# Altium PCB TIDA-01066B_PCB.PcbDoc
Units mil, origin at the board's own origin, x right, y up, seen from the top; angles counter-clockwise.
Board outline 2100 x 1400 mil, 2 copper layers (Top Layer, Bottom Layer), stack 62 mil thick; 43 components, 17 nets, 105 pads, 10 vias.
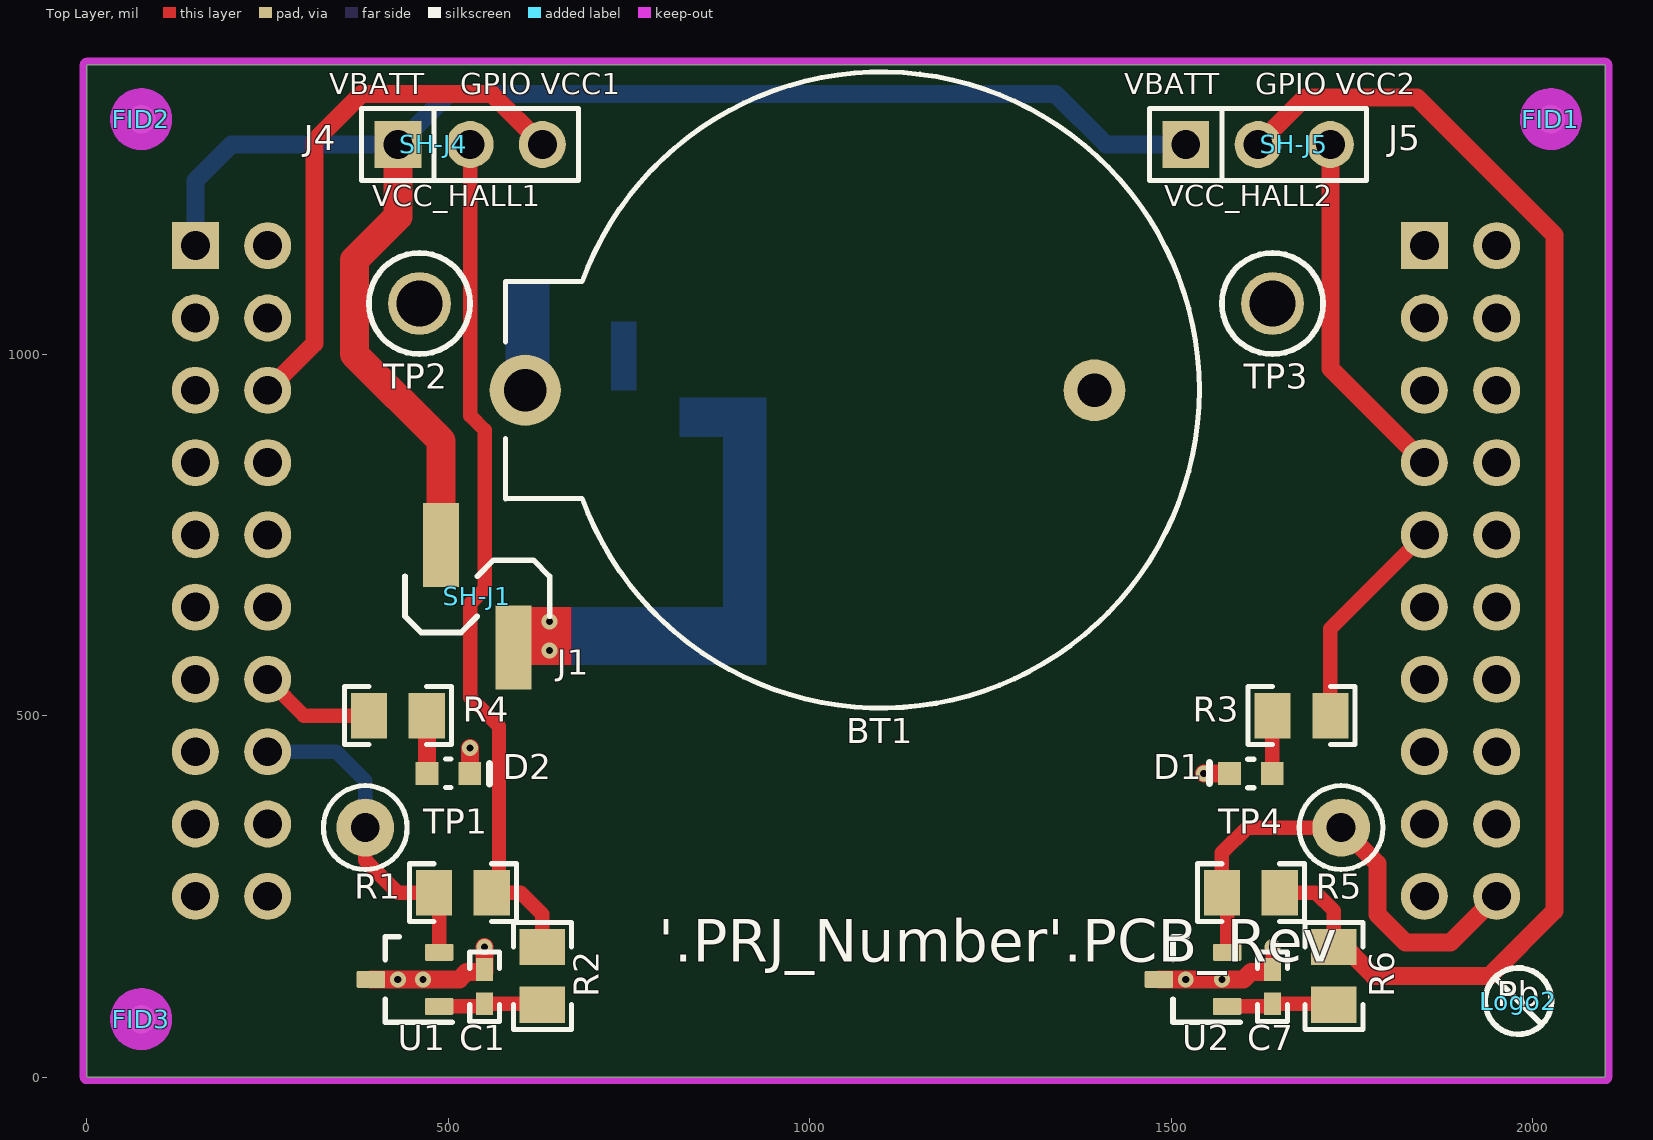
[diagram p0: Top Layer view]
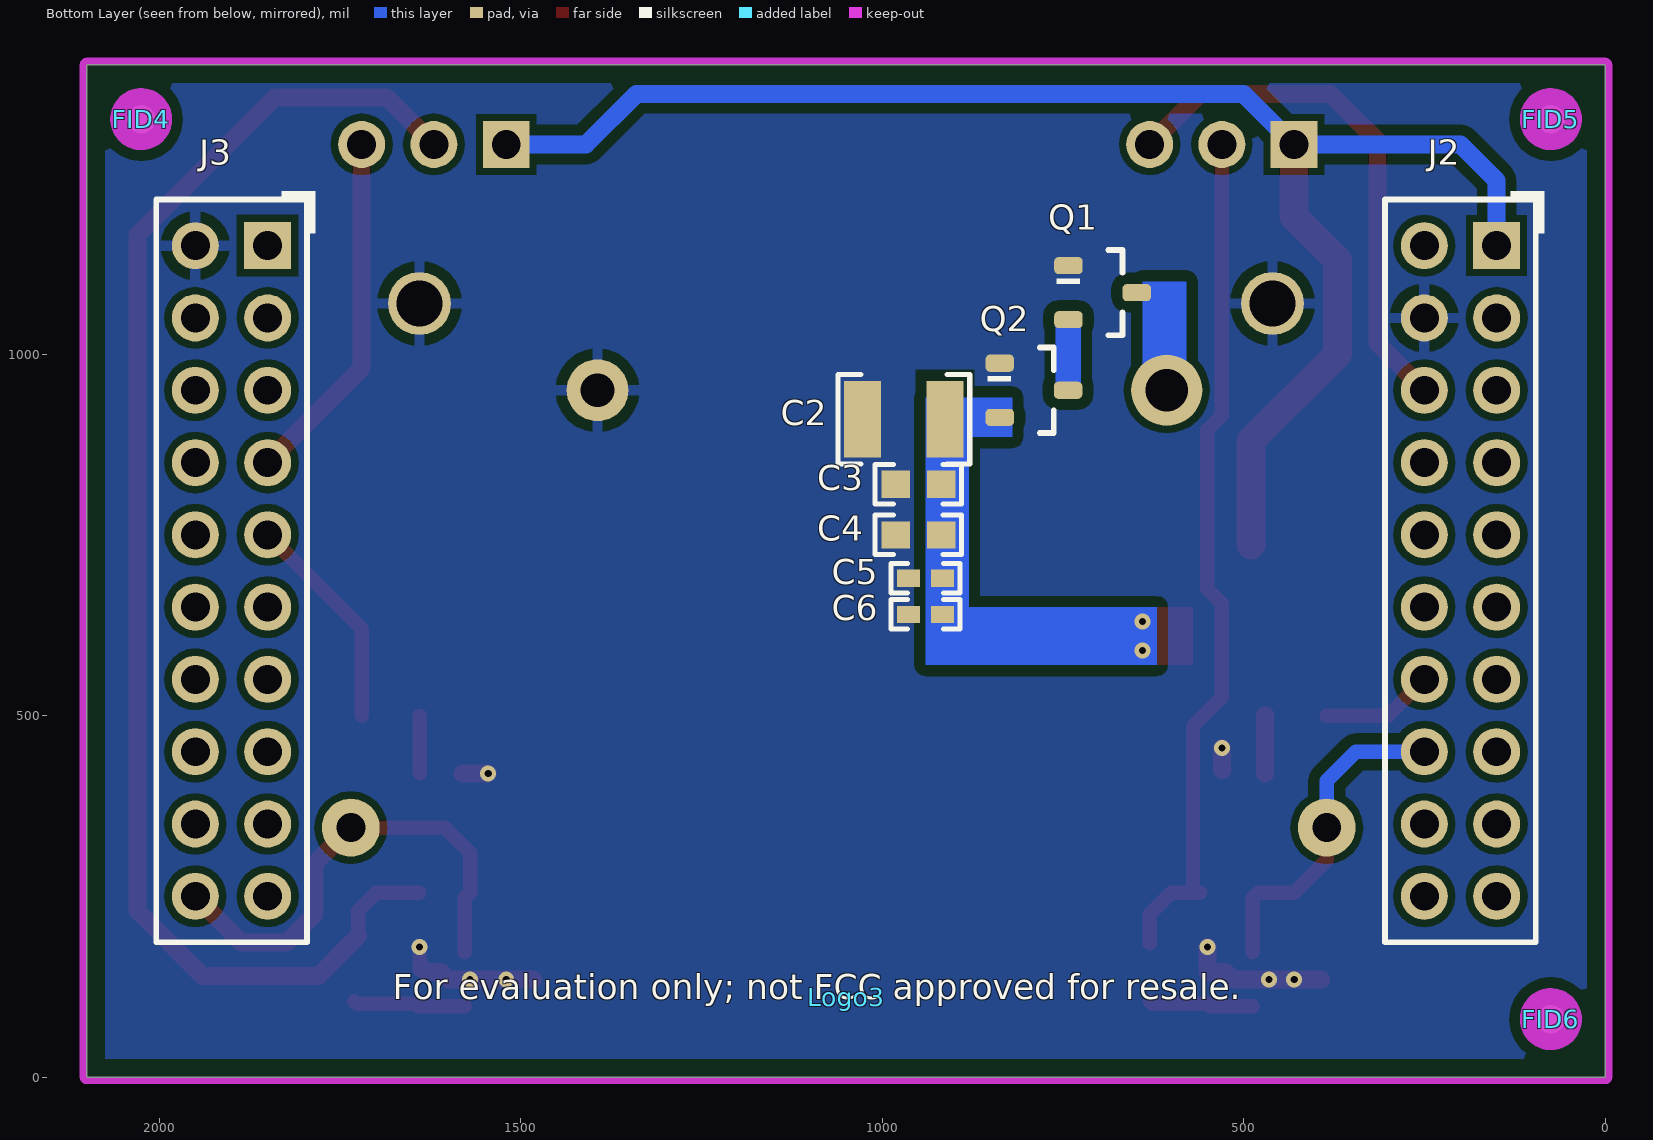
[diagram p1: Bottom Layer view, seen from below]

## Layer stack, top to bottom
Top Solder: solder mask 0.4, Solder Resist, Dk 3.5
Top Layer: signal copper 1.4
Dielectric1: core 59.2, FR-4, Dk 4.8
Bottom Layer: signal copper 1.4
Bottom Solder: solder mask 0.4, Solder Resist, Dk 3.5

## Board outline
0,0 0,1400 2100,1400 2100,0

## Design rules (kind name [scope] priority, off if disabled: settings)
AcuteAngle [All] p1: minimum=4.50000000000000E+0001 checktracksonly=FALSE
AssemblyTestPointUsage [All] p1: valid=2
BoardOutlineClearance BoardOutlineClearance_MountingHoles [OnCopper and InComponentClass('Mounting Holes')] p1: gap=40
BoardOutlineClearance BoardOutlineClearance_Poly [OnCopper and InPoly] p2: gap=25
BoardOutlineClearance [OnCopper and Not InComponentClass('Logo') and not InComponentClass('FiducialMark') and not InRegion(1000,500,4000,800)] p3: gap=25
Clearance Clearance_Keepouts [((IsTrack Or IsArc) And Not InPoly) And IsFree and IsKeepOut vs ((IsTrack Or IsArc) And Not InPoly) And IsFree and IsKeepOut] p1: gap=0
Clearance Clearance_Poly [InPolygon] p2: gap=15 except(10: THPad-Poly)
Clearance [All] p3: gap=7.87
ComponentClearance ComponentClearance_MountingHoles_FiducialMarks [InComponentClass('Mounting Holes') vs InComponentClass('FiducialMark')] p1: gap=50 collisioncheckmode=3 verticalgap=10 showdistances=FALSE
ComponentClearance ComponentClearance_Shunt [InComponentClass('Header') vs InComponentClass('Shunt')] p2: gap=0 collisioncheckmode=3 verticalgap=0 showdistances=FALSE
ComponentClearance ComponentClearance_Logo [InComponentClass('Logo')] p3: gap=0 collisioncheckmode=3 verticalgap=0 showdistances=FALSE
ComponentClearance ComponentClearance_ScrewToNut [(HasFootprint('NY PMS 440 0025 PH')) vs (HasFootprint('Keystone_1902C'))] p4: gap=5 collisioncheckmode=3 verticalgap=10 showdistances=FALSE
ComponentClearance ComponentClearance_MountingHoles [InComponentClass('Mounting Holes')] p5: gap=250 collisioncheckmode=3 verticalgap=100000 showdistances=FALSE
ComponentClearance ComponentClearance_SmallPassives [HasFootprint('0201*') or HasFootprint('0402*') or HasFootprint('0508') or HasFootprint('0603*') or HasFootprint('0612') or HasFootprint('0805*') or HasFootprint('0815*') or HasFootprint('0830*') or HasFootprint('1206*') or HasFootprint('1210*') or HasFootprint('1808*') or HasFootprint('1812*') or HasFootprint('1825*') or HasFootprint('2010*') or HasFootprint('2220*') or HasFootprint('2225*') or HasFootprint('2512*') or HasFootprint('2728*') or HasFootprint('3518*') vs HasFootprint('0201*') or HasFootprint('0402*') or HasFootprint('0508') or HasFootprint('0603*') or HasFootprint('0612') or HasFootprint('0805*') or HasFootprint('0815*') or HasFootprint('0830*') or HasFootprint('1206*') or HasFootprint('1210*') or HasFootprint('1808*') or HasFootprint('1812*') or HasFootprint('1825*') or HasFootprint('2010*') or HasFootprint('2220*') or HasFootprint('2225*') or HasFootprint('2512*') or HasFootprint('2728*') or HasFootprint('3518*')] p6: gap=14.96 collisioncheckmode=3 verticalgap=10 showdistances=FALSE
ComponentClearance ComponentClearance_THtoSMT [IsThruComponent vs IsSMTComponent] p7: gap=40 collisioncheckmode=3 verticalgap=30 showdistances=FALSE
ComponentClearance ComponentClearance_THtoTH [IsThruComponent vs IsThruComponent] p8: gap=30 collisioncheckmode=3 verticalgap=30 showdistances=FALSE
ComponentClearance [All] p9: gap=30 collisioncheckmode=3 verticalgap=10 showdistances=FALSE
DiffPairsRouting [All] p1: maxlimit=100 minlimit=10 mostfreqgap=10 toplayer_minwidth=15 toplayer_maxwidth=15 toplayer_prefwidth=15 bottomlayer_minwidth=15 bottomlayer_maxwidth=15 bottomlayer_prefwidth=15 maxuncoupledlength=1000
FabricationTestPointUsage TestPointUsage [All] p1: valid=2 allowmultiple=FALSE
FabricationTestpoint Testpoint [All] p1: side=3 testpointundercomponent=TRUE minsize=40 maxsize=100 preferedsize=60 minholesize=0 maxholesize=40 preferedholesize=32 testpointgrid=1 allowsidetop=TRUE allowsidebottom=TRUE usegrid=TRUE gridtolerance=0.01
FanoutControl Fanout_LCC [IsLCC] p1: bgadir=Out bgaviamode=Centered fanoutstyle=Auto fanoutdirection=Alternating viagrid=1 // Fanout_LCC (Default Rule)
FanoutControl Fanout_BGA [IsBGA] p2: bgadir=Out bgaviamode=Centered fanoutstyle=Auto fanoutdirection=Alternating viagrid=1 // Fanout_BGA (Default Rule)
FanoutControl Fanout_Default [All] p4: bgadir=Out bgaviamode=Centered fanoutstyle=Auto fanoutdirection=Alternating viagrid=1 // Fanout_Default (Default Rule)
FanoutControl Fanout_Small [(CompPinCount < 5)] p5: bgadir=Out bgaviamode=Centered fanoutstyle=Auto fanoutdirection=OutThenIn viagrid=1 // Fanout_Small (Default Rule)
HoleSize [All] p1: absolutevalues=TRUE maxlimit=251 minlimit=7.87 maxpercent=80.000 minpercent=20.000
MinimumAnnularRing MinimumAnnularRing_ThermalPadVias [IsVia and InAnyComponent] p1: minimumring=5.91
MinimumAnnularRing [All] p2: minimumring=6
MinimumSolderMaskSliver MinimumSolderMaskSliver_Logo [InComponentClass('Logo') vs InComponentClass('Logo')] p1: minsoldermaskwidth=0.7
MinimumSolderMaskSliver [All] p2: minsoldermaskwidth=3.94
PlaneConnect [All] p1: planeconnectstyle=Relief reliefexpansion=10 reliefentries=4 reliefconductorwidth=10 reliefairgap=10
PolygonConnect PolygonConnect_1 [InThruComponent vs ispoly] p1: connectstyle=Relief reliefconductorwidth=15 reliefentries=4 polygonreliefangle="90 Angle" airgapwidth=15
PolygonConnect [All] p2: connectstyle=Direct reliefconductorwidth=10 reliefentries=4 polygonreliefangle="90 Angle" airgapwidth=10
RoutingVias ThermalPadVias [IsVia and InAnyComponent] p1: holewidth=7.87 width=19.68 viastyle="Through Hole" minholewidth=7.87 minwidth=19.68 maxholewidth=12.99 maxwidth=23.62
RoutingVias [All] p2: holewidth=10 width=26 viastyle="Through Hole" minholewidth=7.87 minwidth=22 maxholewidth=40 maxwidth=65
SilkToBoardRegionClearance [Not ((IsComment or IsDesignator) And (Hide <> 'False')) and not InRegion(1000,500,4000,800)] p1:
SilkToSilkClearance SilkToSilkClearance_Pb-FreeLogo [(HasFootprint('Pb-Free_Overlay_Medium') OR HasFootprint('Pb-Free_Overlay_Small')) vs (HasFootprint('Pb-Free_Overlay_Medium') OR HasFootprint('Pb-Free_Overlay_Small'))] p1: silktosilkclearance=0
SilkToSilkClearance [All] p2: silktosilkclearance=4
SilkToSolderMaskClearance SilkToComponentPadClearance [IsPad and InAnycomponent] p1: minsilkscreentomaskgap=5 clearancetoexposedcopper=TRUE
SilkToSolderMaskClearance "Silk to Solder Mask Opening" [All] p2: minsilkscreentomaskgap=4 clearancetoexposedcopper=FALSE
SolderMaskExpansion [All] p1: expansion=1.97
Width [All] p1: maxlimit=100 minlimit=7.8 preferedwidth=10 checkconnectedcopper=TRUE
15 further rules are at their usual default settings.

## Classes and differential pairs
component class AssemblyNote: ZZ2 ZZ3 ZZ4
component class FiducialMark: FID1 FID2 FID3 FID4 FID5 FID6
component class TIDA-01066B_EVM_Hardware: FID1 FID2 FID3 FID4 FID5 FID6 Logo2 Logo3 ZZ2 ZZ3 ZZ4
component class Header: J1 J4 J5
component class Shunt: SH-J1 SH-J4 SH-J5
component class TIDA-01066B_Hall_Effect_Sensor: BT1 C1 C2 C3 C4 C5 C6 C7 D1 D2 J1 J2 J3 J4 J5 Q1 Q2 R1 R2 R3 R4 R5 R6 SH-J1 SH-J4 SH-J5 TP1 TP2 TP3 TP4 U1 U2

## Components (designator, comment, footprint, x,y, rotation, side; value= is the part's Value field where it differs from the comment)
BT1 "BS-7" BAT_BS-7 1000,950 r0 top locked
C1 "GRM155R71C103KA01D" 0402 550,125 r90 top
C2 "GRM32ER60G337ME05L" 1210 970,910 r0 bottom
C3 "C1608X5R0J106M" 0603 950,820 r0 bottom
C4 "C1608X7R1C105K" 0603 950,750 r0 bottom
C5 "C1005X7R1H104K050BB" 0402 940,690 r0 bottom
C6 "C1005X7R1C103K050BA" 0402 940,640 r0 bottom
C7 "GRM155R71C103KA01D" 0402 1640,125 r90 top
D1 "LS L29K-G1J2-1-Z" "LS L29K_Red" 1610,420 r180 top
D2 "LY L29K-H1K2-26-Z" "LY L29K_Yellow" 500,420 r0 top
FID1 "Fiducial" Fiducial10-20 2025,1325 r0 top
FID2 "Fiducial" Fiducial10-20 75,1325 r0 top
FID3 "Fiducial" Fiducial10-20 75,80 r0 top
FID4 "Fiducial" Fiducial10-20 2025,1325 r90 bottom
FID5 "Fiducial" Fiducial10-20 75,1325 r90 bottom
FID6 "Fiducial" Fiducial10-20 75,80 r90 bottom
J1 "87898-0204" Molex_87898-0204 540,665 r180 top
J2 "PPPC102LFBN-RC" Sullins_PPPC102LFBN-RC 200,700 r90 bottom
J3 "PPPC102LFBN-RC" Sullins_PPPC102LFBN-RC 1900,700 r90 bottom
J4 "PBC03SAAN" PBC03SAAN 530,1290 r0 top
J5 "PBC03SAAN" PBC03SAAN 1620,1290 r0 top
Logo2 "Pb-Free Symbol" Pb-Free_Overlay_Small 1980,105 r0 top
Logo3 "FCC disclaimer" FCC_disclaimer 1050,110 r180 bottom
Q1 "SI2323DS" SOT-23 695,1085 r180 bottom
Q2 "SI2323DS" SOT-23 790,950 r180 bottom
R1 "CRCW08051M00JNEA" 0805_HV 520,255 r0 top
R2 "CRCW08050000Z0EA" 0805_HV 630,140 r270 top
R3 "CRCW0805442RFKEA" 0805_HV 1680,500 r0 top
R4 "CRCW0805487RFKEA" 0805_HV 430,500 r180 top
R5 "CRCW08051M00JNEA" 0805_HV 1610,255 r0 top
R6 "CRCW08050000Z0EA" 0805_HV 1725,140 r270 top
SH-J1 "969102-0000-DA" SNT-100-BK-G 540,665 r180 top
SH-J4 "969102-0000-DA" SNT-100-BK-G 480,1290 r180 top
SH-J5 "969102-0000-DA" SNT-100-BK-G 1670,1290 r180 top
TP1 "5004" Keystone5004 385,345 r0 top
TP2 "5011" Keystone5011 460,1070 r0 top
TP3 "5011" Keystone5011 1640,1070 r0 top
TP4 "5004" Keystone5004 1735,345 r0 top
U1 "DRV5032FBDBZR" DBZ0003A_N 440,135 r180 top
U2 "DRV5032FBDBZR" DBZ0003A_N 1530,135 r180 top
ZZ2 "These assemblies are ESD sensitive, ESD precautions shall be observed." AssemblyNote 150,2044.11 r0 top
ZZ3 "These assemblies must be clean and free from flux and all contaminants. Use of no clean flux is not acceptable." AssemblyNote 150,1955.56 r0 top
ZZ4 "These assemblies must comply with workmanship standards IPC-A-610 Class 2, unless otherwise specified." AssemblyNote 150,1867 r0 top

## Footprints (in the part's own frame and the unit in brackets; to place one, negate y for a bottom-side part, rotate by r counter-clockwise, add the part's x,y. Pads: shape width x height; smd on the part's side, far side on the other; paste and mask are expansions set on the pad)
0402 [mm] "0402 from SM-752 data"
  rect 0.8x0.6 smd: 1(-0.6,0) 2(0.6,0)
  silkscreen extent -1.22,-0.52 1.22,0.52, body extent -0.55,-0.3 0.55,0.3, height 0.6
0603 [mm] "0603 from SM-752 data"
  rect 1x0.95 smd: 1(-0.8,0) 2(0.8,0)
  silkscreen extent -1.52,-0.69 1.52,0.69, body extent -0.87,-0.47 0.87,0.47, height 1
0805_HV [mil] "0805 with 30mil clearance between pads"
  rect 50x63 smd: 1(-40,0) 2(40,0)
  silkscreen extent -74,-40 74,40, body extent -43,-29 43,29, height 57
1210 [mm] "1210 from SM-752 data"
  rect 1.3x2.7 smd: 1(-1.45,0) 2(1.45,0)
  silkscreen extent -2.32,-1.57 2.32,1.57, body extent -1.7,-1.35 1.7,1.35, height 1.35
AssemblyNote [mil] "Assembly Note"
BAT_BS-7 [mm] "Memory Protection Devices CR2032 battery holder"
  round 2.5 hole 1.5: 1(-10,0)
  round 2.17 hole 1.181: 2(10,0)
  silkscreen extent -10.7,-11.16 13.68,11.18, body extent -10.69,-11.16 13.7,11.16, height 9.02
DBZ0003A_N [mm] "SOT23, 3-Leads, Body 2.9x1.3mm, Pitch 0.95mm, Lead Span 2.4mm, IPC Medium Density"
  rrect17% 1x0.6 smd: 1(-1.2,0.95) 2(-1.2,-0.95) 3(1.2,0)
  silkscreen extent -1.65,-1.5 0.7,1.5, body extent -1.26,-1.46 1.26,1.46, height 0.98
FCC_disclaimer [mil]
Fiducial10-20 [mm]
  round 1 smd mask+0.5: 1(0,0)
  Top Layer keep-out circle w1.178: c0,0 r0.5
Keystone5004 [mil] "For Keystone 500x miniature loop terminals"
  round 80 hole 40: 1(0,0)
  silkscreen extent -58,-58 58,58, body extent -49,-49 49,49, height 182
Keystone5011 [mil] "Keystone Multipurpose loops"
  round 87 hole 63: 1(0,0)
  silkscreen extent -70,-70 70,70, body extent -63,-63 63,62, height 319
"LS L29K_Red" [mm] "SMD, 2-Leads, Body 1.3x0.8mm"
  rect 0.8x0.8 smd paste-0.4: 1(-0.75,0) 2(0.75,0)
  silkscreen extent -0.1,-0.5 1.45,0.5, body extent -0.9,-0.45 0.9,0.45, height 0.67
"LY L29K_Yellow" [mm] "OSRAM"
  rect 0.8x0.8 smd paste-0.4: 1(-0.75,0) 2(0.75,0)
  silkscreen extent -0.1,-0.5 1.45,0.5, body extent -0.9,-0.45 0.9,0.45, height 0.67
Molex_87898-0204 [mm] "Header, 2.54 mm, 2x1, R/A, SMT"
  rect 1.27x2.96 smd: 1(-1.27,1.8) 2(1.27,-1.8)
  silkscreen extent -2.54,-1.27 2.54,1.27, body extent -2.54,-2.4 2.54,2.4, height 9.65
Pb-Free_Overlay_Small [mil]
  silkscreen extent -46,-46 46,46
PBC03SAAN [mm] "Sullins 100mil, 1x3, 230 mil above insulator"
  rect 1.65x1.65 hole 1.016: 1(-2.54,0)
  round 1.65 hole 1.016: 2(0,0) 3(2.54,0)
  silkscreen extent -3.81,-1.27 3.81,1.27, body extent -3.81,-1.27 3.81,1.27, height 8.38
SNT-100-BK-G [mil] "Samtec STEP model"
  round 1 on Mech3: 0(0,0)
  body extent -100,-50 100,50, height 344
SOT-23 [mm] "SOT23, 3-Leads, Body 2.9x1.3mm, Pitch 0.95mm, Lead Span 2.5mm, IPC Medium Density"
  rrect50% 1x0.6 smd: 1(-1.2,0.95) 2(-1.2,-0.95) 3(1.2,0)
  silkscreen extent -1.63,-1.5 0.7,1.5, body extent -1.16,-1.45 1.21,1.45, height 1
Sullins_PPPC102LFBN-RC [mil] "Sullins"
  rect 65x65 hole 40: 1(450,-50)
  round 65 hole 40: 2(450,50) 3(350,-50) 4(350,50) 5(250,-50) 6(250,50) 7(150,-50) 8(150,50) 9(50,-50) 10(50,50) 11(-50,-50) 12(-50,50) 13(-150,-50) 14(-150,50) 15(-250,-50) 16(-250,50) 17(-350,-50) 18(-350,50) 19(-450,-50) 20(-450,50)
  silkscreen extent -514,-116 526,104, body extent -514,-104 514,104, height 335

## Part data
BT1: "Battery Holder, CR2032, Retainer clip, TH"
C1 C6 C7: "CAP, CERM, 0.01 µF, 16 V, +/- 10%, X7R, 0402"
C2: library part Capacitor, "CAP, CERM, 330 µF, 4 V, X5R, +/- 20%, 1210"
C3: "CAP, CERM, 10 µF, 6.3 V, +/- 20%, X5R, 0603"
C4: "CAP, CERM, 1 µF, 16 V, +/- 10%, X7R, 0603"
C5: "CAP, CERM, 0.1 µF, 50 V, +/- 10%, X7R, 0402"
D1: "LED, Red, SMD"
D2: "LED, Yellow, SMD"
FID1 FID2 FID3 FID4 FID5 FID6: "Fiducial mark.  There is nothing to buy or mount."
J1: "Header, 2.54 mm, 2x1, Gold, R/A, SMT"
J2 J3: "Receptacle, 100mil, 10x2, Gold, TH"
J4 J5: "Header, 100mil, 3x1, Gold, TH"
Logo2: library part Pb-Free
Logo3: library part FCC_disclaimer, "FCC_disclaimer"
Q1 Q2: "MOSFET, P-CH, -20 V, -3.7 A, SOT-23"
R1 R5: "RES, 1.0 M, 5%, 0.125 W, 0805"
R2 R6: "RES, 0, 5%, 0.125 W, 0805"
R3: "RES, 442, 1%, 0.125 W, 0805"
R4: "RES, 487, 1%, 0.125 W, 0805"
SH-J1 SH-J4 SH-J5: "Shunt, 100mil, Gold plated, Black"
TP1 TP4: "Test Point, Miniature, Yellow, TH"
TP2 TP3: "Test Point, Multipurpose, Black, TH"
U1 U2: "Ultra-Low Power Digital-Switch Hall Effect Sensor, DBZ0003A"
ZZ2 ZZ3 ZZ4: library part AssemblyNote

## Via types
v1: diameter 22, hole 10, Top Layer to Bottom Layer, tented both sides, 10 vias

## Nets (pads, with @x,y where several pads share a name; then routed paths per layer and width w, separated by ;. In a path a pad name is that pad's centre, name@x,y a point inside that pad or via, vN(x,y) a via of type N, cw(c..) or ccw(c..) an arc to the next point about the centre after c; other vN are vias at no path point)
GND: BT1.2 C1.2 C2.2 C3.2 C4.2 C5.2 C6.2 C7.2 D1.2 D2.2 J2.4 J3.2 Q1.1 Q2.1 TP2.1 TP3.1 U1.3 U2.3 | length 448.3
  Top Layer w20: C7.2 v1(1640,180)
  Top Layer w25: U1.3 v1(430,135) v1(465,135) 515,135 525,145 C1.2@550,145 ; D2.2@529.53,425 530,425.47 v1(530,455) ; C1.2 v1(550,180) ; U2.3 v1(1520,135) v1(1570,135) 1600,135 1610,145 1630,145 C7.2@1635,150 ; v1(1545,420) D1.2
GPIO_VCC1: J2.6 J4.3 | length 742.8
  Top Layer w25: J2.6 315,1015 315,1295 380,1360 560,1360 J4.3
GPIO_VCC2: J3.7 J5.3 | length 493.8
  Top Layer w25: J5.3 1720,980 J3.7
HALL1_OUT: J2.16 R1.1 TP1.1 U1.2 | length 460.8
  Top Layer w20: TP1.1 385,300 430,255 R1.1 487.24,247.76 U1.2
  Bottom Layer w20: J2.16 345,450 385,410 TP1.1
HALL2_OUT: J3.20 R5.1 TP4.1 U2.2 | length 699.5
  Top Layer w20: U2.2 1577.24,247.76 R5.1 1570,310 1605,345 TP4.1
  Top Layer w25: TP4.1 1785,295 1785,225 1823.78,186.22 1886.22,186.22 J3.20
  Bottom Layer w20: TP4.1@1730,330 1735,335 TP4.1@1745,345
  Bottom Layer w25: TP4.1@1735,335 TP4.1
NetBT1_1: BT1.1 Q1.3
NetC1_1: C1.1 R2.2 U1.1 | length 145.8
  Top Layer w20: U1.1 546.22,97.6 C1.1 626.38,101.38 R2.2@630,105
NetC2_1: C2.1 C3.1 C4.1 C5.1 C6.1 J1.1 Q2.2
  other v1: 640,590 640,630
NetC7_1: C7.1 R6.2 U2.1 | length 155.8
  Top Layer w20: U2.1 1642.05,97.6 1645.83,101.38 1726.38,101.38 R6.2@1730,105
NetD1_1: D1.1 R3.1 | length 80.2
  Top Layer w20: D1.1 1639.53,499.53 R3.1
NetD2_1: D2.1 R4.1 | length 80.2
  Top Layer w25: R4.1 470.47,499.53 D2.1
NetQ1_2: Q1.2 Q2.3
RLED: J3.9 R3.2 | length 303.8
  Top Layer w20: R3.2 1720,620 J3.9
V_BATT: J1.2 J2.1 J4.1 J5.1 | length 2142.4
  Top Layer w40: J4.1 430,1190 370,1130 370,1000 490,880 J1.2
  Bottom Layer w25: J2.1@150,1175 150,1240 200,1290 J4.1 500,1360 1340,1360 1410,1290 J5.1
VCC_HALL1: J4.2 R1.2 R2.1 | length 1180.6
  Top Layer w20: J4.2 530,915 550,895 550,675 530,655 530,525 570,485 R1.2@570,265 ; R1.2 600,255 630,225 R2.1@630,185
VCC_HALL2: J5.2 R5.2 R6.1 | length 1946
  Top Layer w20: R5.2@1640,255 R5.2 1700,255 1725,230 R6.1@1725,195
  Top Layer w25: J5.2 1685,1355 1840,1355 2030,1165 2030,230 1940,140 1780,140 R6.1@1725,195
YLED: J2.14 R4.2 | length 155.7
  Top Layer w20: J2.14 300,500 R4.2@385,500
pads on no net: FID1.1 FID2.1 FID3.1 FID4.1 FID5.1 FID6.1 J2.2 J2.3 J2.5 J2.7 J2.8 J2.9 J2.10 J2.11 J2.12 J2.13 J2.15 J2.17 J2.18 J2.19 J2.20 J3.1 J3.3 J3.4 J3.5 J3.6 J3.8 J3.10 J3.11 J3.12 J3.13 J3.14 J3.15 J3.16 J3.17 J3.18 J3.19 SH-J1.0 SH-J4.0 SH-J5.0

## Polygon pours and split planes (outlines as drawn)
GND on Bottom Layer "Top Layer-No Net" (solid, remove dead copper, pour order 0): 25,1375 2075,1375 2075,25 25,25

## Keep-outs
Keep-Out Layer:
  lines w10: -5,0 ccw(c0,0) 0,-5 ; -5,0 ccw(c0,0) 0,-5 ; -5,0 -5,1400 ; -5,1400 cw(c0,1400) 0,1405 ; -5,1400 cw(c0,1400) 0,1405 ; 0,-5 2100,-5 ; 0,1405 2100,1405 ; 2100,-5 ccw(c2100,0) 2105,0 ; 2100,-5 ccw(c2100,0) 2105,0 ; 2100,1405 cw(c2100,1400) 2105,1400 ; 2100,1405 cw(c2100,1400) 2105,1400 ; 2105,0 2105,1400
  text ".Layer_Name" at 577,-858.49 h60

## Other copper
Top Layer:
  rectangle net NetC2_1: 570,570 670,650
  text ".Layer_Name" at 577,-858.49 h60
Bottom Layer:
  rectangle net NetBT1_1: 578.74,935 640,1100.39
  rectangle net NetQ1_2: 725,950 760,1045
  rectangle net NetC2_1: 620,570 920,650
  rectangle net NetC2_1: 880,570 940,940
  rectangle net NetC2_1: 820,885 940,940
  text ".Layer_Name" at 577,-858.49 h60

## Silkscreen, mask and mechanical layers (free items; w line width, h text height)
Top Overlay:
  text "VBATT    GPIO VCC1" at 335,1350 h50
  text "VBATT    GPIO VCC2" at 1435,1350 h50
  text "VCC_HALL1" at 395,1195 h50
  text "VCC_HALL2" at 1490,1195 h50
  text "'.PRJ_Number'.PCB_Rev" at 790,140 h100
  text ".Layer_Name" at 577,-858.49 h60
Bottom Overlay:
  text ".Layer_Name" at 577,-858.49 h60
Top Paste:
  text ".Layer_Name" at 577,-858.49 h60
Bottom Paste:
  text ".Layer_Name" at 577,-858.49 h60
Top Solder:
  text ".Layer_Name" at 577,-858.49 h60
  text ".Layer_Name" at 577,-858.49 h60
Bottom Solder:
  text ".Layer_Name" at 577,-858.49 h60
Drill Guide:
  text ".Layer_Name" at 577,-858.49 h60
M1 Board Outline:
  the board outline again, w10
  text ".Layer_Name" at 577,-858.49 h60
M2 Board Dimensions:
  rectangle: 125,-400 500,-275
  rectangle: 0,-275 125,-150
  lines w7: 0,-275 1000,-275 ; 125,-400 125,-150 ; 250,-400 250,-150 ; 500,-400 500,-150 ; 750,-400 750,-150 ; 0,-400 0,-150 1000,-150 1000,-400 0,-400
  text ".Layer_Name" at 577,-858.49 h60
M3 3D STEP Top:
  text ".Layer_Name" at 577,-858.49 h60
M4 3D STEP Bottom:
  text ".Layer_Name" at 577,-858.49 h60
M5 Assembly Top:
  lines w10: -292,-930.17 6308,-930.17 ; -292,-726.83 6310,-726.83 ; -292,-523.5 -292,-1133.5 3713,-1133.5 6310,-1133.5 6310,-523.5 -291.5,-523.5 -291.5,-1133.5 1284,-1133.5 ; 2173,-1133.5 2173,-523.5 ; 3440,-726.83 3440,-523.5 ; 4280,-726.83 4280,-523.5 ; 4902,-1140 4902,-937.17
  text "COMPONENTS MARKED 'DNP' SHOULD NOT BE POPULATED." at 1153.5,-318.5 h60
  text "ASSEMBLY VARIANT:" at 1153,-434 h60
  text ".VariantName" at 2189,-434 h60
  text "PCB VIEWED FROM TOP SIDE" at -228.5,-655.67 h60
  text "BOARD #:" at 2248,-655.67 h60
  text ".PRJ_Number" at 2793.5,-655.67 h60
  text "REV:" at 3638,-655.67 h60
  text ".PCB_Rev" at 3929.5,-655.67 h60
  text "SVN REV:" at 4476,-655.67 h60
  text ".VersionControl_RevNumber" at 4982,-655.67 h60
  text "TID #:" at 2248,-859 h60
  text ".TID" at 2793.5,-859 h60
  text "PLOT NAME =" at -228.5,-1064.34 h60
  text ".plot_File_Name" at 577,-1064.34 h60
  text "GENERATED    :" at 2250,-1064.34 h60
  text ".Print_Date" at 3119.5,-1064.34 h60
  text ".Print_Time" at 3848.5,-1064.34 h60
  text "TEXAS INSTRUMENTS" at 5113,-1064.34 h60
M6 Assembly Bottom:
  lines w10: -292.5,-727.33 6309.5,-727.33 ; -290.5,-930.67 6309.5,-930.67 ; 1115.5,-1140.5 1115.5,-937.67 ; 1737.5,-727.33 1737.5,-524 ; 2577.5,-727.33 2577.5,-524 ; 3844.5,-1134 3844.5,-524 ; 4733.5,-1134 6309,-1134 6309,-524 -292.5,-524 -292.5,-1134 2304.5,-1134 6309.5,-1134 6309.5,-524
  text "COMPONENTS MARKED 'DNP' SHOULD NOT BE POPULATED." at 6102,-318 h60
  text ".VariantName" at 5058,-434 h60
  text "ASSEMBLY VARIANT:" at 6097,-434 h60
  text ".VersionControl_RevNumber" at 1035.5,-656.17 h60
  text "SVN REV:" at 1541.5,-656.17 h60
  text ".PCB_Rev" at 2088,-656.17 h60
  text "REV:" at 2379.5,-656.17 h60
  text ".PRJ_Number" at 3224,-656.17 h60
  text "BOARD #:" at 3769.5,-656.17 h60
  text "PCB VIEWED FROM BOTTOM SIDE" at 6246,-656.17 h60
  text ".TID" at 3224,-859.5 h60
  text "TID #:" at 3769.5,-859.5 h60
  text "TEXAS INSTRUMENTS" at 904.5,-1064.84 h60
  text ".Print_Time" at 2169,-1064.84 h60
  text ".Print_Date" at 2898,-1064.84 h60
  text "GENERATED    :" at 3767.5,-1064.84 h60
  text ".plot_File_Name" at 5440.5,-1064.84 h60
  text "PLOT NAME =" at 6246,-1064.84 h60
M9 Title Sheet:
  drawing of 57 lines, arcs and shapes, not listed
  text "1" at 739.84,8036.5 h70
  text "2" at 3235.5,8036.5 h70
  text "3" at 5724.84,8036.5 h70
  text "4" at 8231.51,8036.5 h70
  text "5" at 10730.5,8036.5 h70
  text "6" at 13235.5,8036.5 h70
  text "A" at -416.5,6893.5 h70
  text "A" at 14383.5,6893.5 h70
  text "B" at -416.5,4513.5 h70
  text "B" at 14383.5,4513.5 h70
  text "C" at -416.5,2138.5 h70
  text "C" at 14383.5,2138.5 h70
  text "PROJECT TITLE:" at 11343.5,277.5 h45
  text ".PRJ_Title" at 11393.5,144.17 h70
  text "DESIGNED FOR:" at 11343.5,-23.5 h45
  text ".PRJ_Customer" at 11393.5,-163.5 h70
  text "D" at -416.5,-231.5 h70
  text "D" at 14383.5,-231.5 h70
  text "FILE NAME:" at 11343.5,-323.5 h45
  text ".PCB_File_Name_No_Path" at 11393.5,-443.5 h70
  text "Texas Instruments (TI) and/or its licensors do not warrant the accuracy or completeness of this specification" at 6374,-605.34 h45
  text "ENGINEER:" at 11343.5,-613.5 h45
  text "LAYOUT BY:" at 12848.5,-613.5 h45
  text "or any information contained therein. TI and/or its licensors do not warrant that this design will meet" at 6329.01,-718 h45
  text ".PRJ_Engineer" at 11393.5,-768.49 h70
  text ".PCB_Layout" at 12899,-768.49 h70
  text "the specifications, will be suitable for your application or fit for any particular purpose, or will operate in" at 6329.01,-830.67 h45
  text ".Layer_Name" at 577,-858.49 h60
  text "ALTIUM DESIGNER VERSION:" at 12848.5,-923.5 h45
  text "an implementation. TI and/or its licensors do not warrant that the design is production worthy. You should" at 6329.01,-943.33 h45
  text "completely validate and test your design implementation to confirm the system functionality for your application." at 6374,-1056 h45
  text ".print_Scale" at 11393.5,-1056.83 h70
  text ".Application_BuildNumber" at 12899,-1056.83 h70
  text "1" at 739.84,-1263.5 h70
  text "2" at 3235.5,-1263.5 h70
  text "3" at 5724.84,-1263.5 h70
  text "4" at 8231.51,-1263.5 h70
  text "5" at 10730.5,-1263.5 h70
  text "6" at 13235.5,-1263.5 h70
M10 Fab Notes:
  drawing of 173 lines, arcs and shapes, not listed
  text "DESIGN INFORMATION" at 12378.02,6201 h60
  text "MIN. TRACK WIDTH:" at 11733.46,6021 h60
  text "8" at 12829.7,6021 h60
  text "MIL" at 12984.46,6021 h60
  text "MIN. CLEARANCE:" at 11733.46,5889 h60
  text "0.2" at 12769.7,5889 h60
  text "mm" at 12984.46,5889 h60
  text "MIN. VIA PAD SIZE:" at 11733.46,5757 h60
  text "22" at 12799.71,5757 h60
  text "MIL" at 12984.46,5757 h60
  text "0.05mm (2MIL)" at 12428.46,5615.29 h60
  text "MINIMUM ANNULAR RING" at 11404.23,5611 h60
  text "EXTERNAL" at 13136.46,5611 h60
  text "PER" at 11604.23,5493 h60
  text "IPC-D-275 CLASS 2 LEVEL C" at 11824.23,5493 h60
  text "MIL, HOLES" at 13312.46,5380.71 h60
  text "+/-" at 12920,5380 h60
  text "+/-" at 13774,5380 h60
  text "REGISTRATION TOLERANCES:" at 11404.23,5375 h60
  text "METAL" at 12604,5375 h60
  text "5" at 13180.2,5375 h60
  text "3" at 14013.2,5375 h60
  text "MIL" at 14129.46,5375 h60
  text "+/-" at 13774,5262 h60
  text "HOLE SIZE TOLERANCE (UNLESS OTHERWISE SPECIFIED):" at 11404.23,5257 h60
  text "3" at 14013.2,5257 h60
  text "MIL" at 14129.46,5257 h60
  text "MATERIAL:" at 11329.46,5047.54 h60
  text "FR-4 High Tg" at 12315.9,4907.21 h60
  text "FR-408" at 11750.46,4898.64 h60
  text "OTHER" at 13238.46,4898.64 h60
  text "X" at 12161,4895 h60
  text "62 MIL (1.6mm) +/-10%" at 12070.56,4735.92 h60
  text "THICKNESS:" at 11404.23,4731.64 h60
  text "X" at 11942.4,4731.64 h60
  text "OTHER" at 13355.46,4731.64 h60
  text "TOLERANCE:" at 11404.23,4573.64 h60
  text "X" at 12243.53,4573.64 h60
  text "ANSI IPC-6012 TYPE 3 CLASS 2" at 12430.48,4573.64 h60
  text "OTHER +/-" at 12430.46,4417.64 h60
  text "BOW & TWIST:" at 11404.23,4260.64 h60
  text "X" at 12243.53,4260.64 h60
  text "ANSI IPC-6012 TYPE 3 CLASS 2" at 12430.48,4260.64 h60
  text "OTHER +/-" at 12430.46,4102.13 h60
  text "DRILLING:" at 11329.46,3963.64 h60
  text "REFERENCE:" at 11404.23,3846.64 h60
  text "X" at 12052.46,3846.64 h60
  text "AS SHOWN" at 12239.46,3846.64 h60
  text "X" at 12953.46,3846.64 h60
  text "NC_DRILL FILES" at 13090.46,3846.64 h60
  text "PTH COPPER THICKNESS:" at 11404.23,3688.64 h60
  text "X" at 12534.46,3688.64 h60
  text "20-30 um" at 12671.46,3688.64 h60
  text "OTHER" at 13388.46,3688.64 h60
  text "BOARD FINISH:" at 11329.46,3529.64 h60
  text "SILKSCREEN:" at 11484.68,3411.64 h60
  text "X" at 12433.46,3411.64 h60
  text "TOP" at 12559.46,3411.64 h60
  text "X" at 12943.46,3411.64 h60
  text "BOTTOM" at 13070.46,3411.64 h60
  text "SILKSCREEN COLOR:" at 11484.68,3244.64 h60
  text "X" at 12432.42,3244.64 h60
  text "WHITE" at 12559.46,3244.64 h60
  text "OTHER" at 13070.46,3244.64 h60
  text "X" at 12563.42,3085.44 h60
  text "GREEN" at 12690.46,3085.44 h60
  text "OTHER" at 13308.46,3085.44 h60
  text "SOLDER RESIST COLOR:" at 11484.68,3074.64 h60
  text "X" at 12563.42,2915.44 h60
  text "MATTE" at 12690.46,2915.44 h60
  text "SEMI-GLOSS" at 13308,2914.8 h60
  text "IMMERSION GOLD (ENIG)" at 12390.46,2726.92 h60
  text "ENEPIG" at 13728,2723.64 h60
  text "SURFACE FINISH:" at 11329.46,2722.64 h60
  text "X" at 12203.51,2722.64 h60
  text "IMM. TIN/SILVER OR EQUIV" at 11659,2565.64 h60
  text "OTHER" at 13090.46,2565.64 h60
  text "ARRAY/PANEL:" at 11329.46,2386.64 h60
  text "CUT AND TRIM PER M1 BOARD OUTLINE" at 12390.46,2382.35 h60
  text "N.C. ROUTE" at 12390.46,2230.64 h60
  text "X" at 13069.46,2230.64 h60
  text "V. SCORE" at 13256.46,2230.64 h60
  text "CERTIFICATION:" at 11329.46,2093.64 h60
  text "MATERIALS AND WORKMANSHIP FOR ALL PCBS" at 12054.46,2093.64 h60
  text "TO MEET OR EXCEED THE REQUIREMENTS OF:" at 12054.46,1995.64 h60
  text "X" at 11680.96,1859.13 h60
  text "ANSI IPC-A-600F CLASS ->" at 11819.96,1859.13 h60
  text "X" at 13459.02,1859.13 h60
  text "2" at 13577.96,1859.14 h60
  text "1" at 13262.96,1857.64 h60
  text "3" at 13931.96,1857.64 h60
  text "X" at 12495.02,1699.64 h60
  text "RoHS" at 12631.96,1699.64 h60
  text "OTHER" at 13276.36,1699.64 h60
  text "PER ORDER" at 13673.42,1699.64 h60
  text "ALL BOARDS MUST MEET OR EXCEED UL94-V0 REQUIREMENTS." at 11357,1534 h60
  text "PCB MUST BEAR THE UL94V-0 UL REGISTERED MATERIAL ID NUMBER" at 11357,1414 h60
  text "ADDITIONAL REQUIREMENTS:" at 11329.46,1240.64 h60
  text "MICROSECTION:" at 11404.23,1125.64 h60
  text "YES" at 12309.96,1125.64 h60
  text "REQUIRED" at 13171.46,969.49 h60
  text "BARE BOARD ELEC. TEST:" at 11404.23,966.64 h60
  text "NONE" at 12709.96,966.64 h60
  text "X" at 13044.46,966.64 h60
  text "PER ORDER" at 13763.46,966.64 h60
  text ".Layer_Name" at 577,-858.49 h60
M11 Gerber Information:
  lines w10: -292,-930.17 6308,-930.17 ; -292,-726.83 6310,-726.83 ; -292,-523.5 -292,-1133.5 3713,-1133.5 6310,-1133.5 6310,-523.5 -291.5,-523.5 -291.5,-1133.5 1284,-1133.5 ; 2173,-1133.5 2173,-523.5 ; 3440,-726.83 3440,-523.5 ; 4280,-726.83 4280,-523.5 ; 4902,-1140 4902,-937.17
  text "ALL ARTWORK VIEWED FROM TOP SIDE" at -228.5,-655.67 h60
  text "BOARD #:" at 2248,-655.67 h60
  text ".PRJ_Number" at 2793.5,-655.67 h60
  text "REV:" at 3638,-655.67 h60
  text ".PCB_Rev" at 3929.5,-655.67 h60
  text "SVN REV:" at 4476,-655.67 h60
  text ".VersionControl_RevNumber" at 4982,-655.67 h60
  text "LAYER NAME =" at -228.5,-858.49 h60
  text "TID #:" at 2248,-859 h60
  text ".TID" at 2793.5,-859 h60
  text "PLOT NAME =" at -228.5,-1064.34 h60
  text ".plot_File_Name" at 577,-1064.34 h60
  text "GENERATED    :" at 2250,-1064.34 h60
  text ".Print_Date" at 3119.5,-1064.34 h60
  text ".Print_Time" at 3848.5,-1064.34 h60
  text "TEXAS INSTRUMENTS" at 5113,-1064.34 h60
M12 Stackup:
  drawing of 191 lines, arcs and shapes, not listed
  text "Layer" at 9790.34,7830 h60
  text "Name" at 10200.26,7830 h60
  text "Material" at 11130,7830 h60
  text "Thickness" at 11989.77,7830 h60
  text "Constant" at 12639.6,7830 h60
  text "Board Layer Stack" at 13209.46,7830 h60
  text "1" at 9790.34,7710 h60
  text "Top Overlay" at 10200.26,7710 h60
  text "2" at 9790.34,7590 h60
  text "Top Solder" at 10200.26,7590 h60
  text "Solder Resist" at 11130,7590 h60
  text "0.40mil" at 11989.77,7590 h60
  text "3.5" at 12639.6,7590 h60
  text "3" at 9790.34,7470 h60
  text "Top Layer" at 10200.26,7470 h60
  text "Copper" at 11130,7470 h60
  text "1.40mil" at 11989.77,7470 h60
  text "4" at 9790.34,7350 h60
  text "Dielectric1" at 10200.26,7350 h60
  text "FR-4" at 11130,7350 h60
  text "59.20mil" at 11989.77,7350 h60
  text "4.8" at 12639.6,7350 h60
  text "5" at 9790.34,7230 h60
  text "Bottom Layer" at 10200.26,7230 h60
  text "Copper" at 11130,7230 h60
  text "1.40mil" at 11989.77,7230 h60
  text "6" at 9790.34,7110 h60
  text "Bottom Solder" at 10200.26,7110 h60
  text "Solder Resist" at 11130,7110 h60
  text "0.40mil" at 11989.77,7110 h60
  text "3.5" at 12639.6,7110 h60
  text "7" at 9790.34,6990 h60
  text "Bottom Overlay" at 10200.26,6990 h60
  text ".Layer_Name" at 577,-858.49 h60
M13 Component Bodies Top:
  text ".Layer_Name" at 577,-858.49 h60
M14 Component Bodies Bottom:
  text ".Layer_Name" at 577,-858.49 h60
M15 Courtyards Top:
  text ".Layer_Name" at 577,-858.49 h60
M16 Courtyards Bottom:
  text ".Layer_Name" at 577,-858.49 h60
Drill Drawing:
  lines w10: 5336.09,2741.38 5363.72,2755.19 5391.34,2741.38 5377.53,2769 5391.34,2796.63 5363.72,2782.82 5336.09,2796.63 5349.9,2769 5336.09,2741.38 ; 5336.09,2920.95 5391.34,2920.95 5363.72,2865.7 5336.09,2920.95 ; 5336.09,3003.83 5349.9,3003.83 5363.72,2990.02 5377.53,3003.83 5391.34,3003.83 5377.53,3017.64 5391.34,3031.46 5377.53,3031.46 5363.72,3045.27 5349.9,3031.46 5336.09,3031.46 5349.9,3017.64 5336.09,3003.83 ; 5336.09,3114.34 5391.34,3114.34 5391.34,3169.59 5336.09,3169.59 5336.09,3114.34 ; 5336.09,3252.47 5349.9,3252.47 5349.9,3238.66 5377.53,3238.66 5377.53,3252.47 5391.34,3252.47 5391.34,3280.1 5377.53,3280.1 5377.53,3293.91 5349.9,3293.91 5349.9,3280.1 5336.09,3280.1 5336.09,3252.47
  lines w12: 5286,2704.08 8517.49,2704.08 ; 5286,3325.68 8517.49,3325.68 ; 5623.86,2579.76 5623.86,3450 ; 5955.86,2579.76 5955.86,3450 ; 6592.43,2579.76 6592.43,3450 ; 6851.57,2579.76 6851.57,3450 ; 7226.72,2579.76 7226.72,3450 ; 7951.05,2579.76 7951.05,3450 ; 5286,2579.76 8517.49,2579.76 8517.49,3450 5286,3450 5286,2579.76
  text "Symbol" at 5360.59,3362.98 h72
  text "Quantity" at 5661.16,3362.98 h72
  text "Finished Hole Size" at 5993.16,3362.98 h72
  text "Plated" at 6629.72,3362.98 h72
  text "Hole Type" at 6888.86,3362.98 h72
  text "Drill Layer Pair" at 7264.02,3362.98 h72
  text "Hole Tolerance" at 7988.35,3362.98 h72
  text "10" at 5661.16,3238.66 h60
  text "10.00mil (0.254mm)" at 5993.16,3238.66 h60
  text "PTH" at 6629.72,3238.66 h60
  text "Round" at 6888.86,3238.66 h60
  text "Top Layer - Bottom Layer" at 7264.02,3238.66 h60
  text "48" at 5661.16,3114.34 h60
  text "40.00mil (1.016mm)" at 5993.16,3114.34 h60
  text "PTH" at 6629.72,3114.34 h60
  text "Round" at 6888.86,3114.34 h60
  text "Top Layer - Bottom Layer" at 7264.02,3114.34 h60
  text "1" at 5661.16,2990.02 h60
  text "46.50mil (1.181mm)" at 5993.16,2990.02 h60
  text "PTH" at 6629.72,2990.02 h60
  text "Round" at 6888.86,2990.02 h60
  text "Top Layer - Bottom Layer" at 7264.02,2990.02 h60
  text "1" at 5661.16,2865.7 h60
  text "59.06mil (1.500mm)" at 5993.16,2865.7 h60
  text "PTH" at 6629.72,2865.7 h60
  text "Round" at 6888.86,2865.7 h60
  text "Top Layer - Bottom Layer" at 7264.02,2865.7 h60
  text "2" at 5661.16,2741.38 h60
  text "63.00mil (1.600mm)" at 5993.16,2741.38 h60
  text "PTH" at 6629.72,2741.38 h60
  text "Round" at 6888.86,2741.38 h60
  text "Top Layer - Bottom Layer" at 7264.02,2741.38 h60
  text "62 Total" at 5661.16,2617.06 h60
  text ".Layer_Name" at 577,-858.49 h60
M17 Embedded Cavity:
  text ".Layer_Name" at 577,-858.49 h60
M18 Embedded Assembly:
  text ".Layer_Name" at 577,-858.49 h60
M19 Embedded Keepout:
  text ".Layer_Name" at 577,-858.49 h60

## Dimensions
0,0 to 0,1400 on M2 Board Dimensions
0,0 to 2100,0 on M2 Board Dimensions
0,-400 to 1000,-400 on M2 Board Dimensions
